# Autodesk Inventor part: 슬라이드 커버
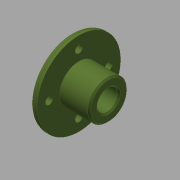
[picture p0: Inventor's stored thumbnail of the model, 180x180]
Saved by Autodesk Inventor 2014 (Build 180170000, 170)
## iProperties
Created: 2015-12
Part Number: 슬라이드 커버
Document SubType Name: Modeling
Designer: mdu
Density: 2.71 g/cm^3
Material: 알루미늄 6061
Appearance: 알루미늄 - 평지
Author: mdu
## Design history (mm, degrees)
sketch "스케치1"
  geometry: L1 (-12.5, 0)-(12.5, 0); L2 (-12.5, 0)-(-12.5, 28); L3 (-12.5, 28)-(-7.5, 28); L4 (-7.5, 28)-(-7.5, 13); L5 (-7.5, 13)-(12.5, 13); L6 (12.5, 13)-(12.5, 0); 2 further points
  constraints: 12 end point, 3 perpendicular, 1 coincident, 1 horizontal, 1 midpoint, 1 parallel
  dimensions: "d1" = 56 diameter of L3 L1; "d2" = 26 diameter of L5 L1; "d5" = 5 distance of L2.end L3.end; "d32" = 20 distance of L4.end L5.end
revolve "회전1" sketch "스케치1" stored, may be unused: angle "d6" = 90 deg
sketch "스케치2" dims "d33" = 40
  geometry: 3 further points
  constraints: 2 vertical alignment, 1 coincident, 2 other
hole "구멍1" sketch "스케치2" at (0, 20) diameter "d8" = 5; stored, may be unused: countersink angle "d12" = 90 deg, drill point angle "d14" = 118 deg; dims "d9" = 6, "d10" = 8, "d11" = 4.4, "d13" = 8
hole "구멍2" diameter "d20" = 14; stored, may be unused: countersink angle "d24" = 90 deg, drill point angle "d26" = 0 deg; dims "d18" = 10, "d19" = 10, "d21" = 6, "d22" = 8, "d23" = 4.4, "d25" = 8
fillet "모깎기1" dims "d27" = 3
chamfer "모따기1" distance "d29" = 1; stored, may be unused: second distance "d30" = 2, angle "d31" = 45 deg
node "솔리드1"
pattern_circular "원형 패턴1" dims angle "d16" = 360 deg
